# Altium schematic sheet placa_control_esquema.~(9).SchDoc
size A4
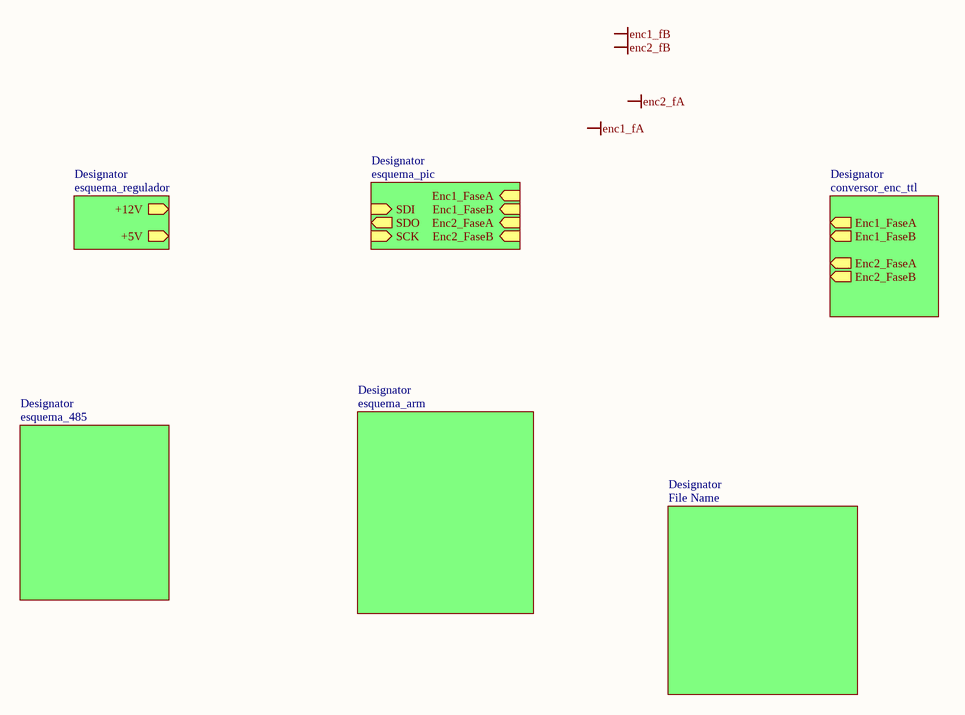
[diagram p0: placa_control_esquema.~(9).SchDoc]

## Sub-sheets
Designator = esquema_regulador: +12V (out), +5V (out)
Designator = esquema_pic: SDI (in), SDO (out), SCK (in), Enc1_FaseA (in), Enc1_FaseB (in), Enc2_FaseA (in), Enc2_FaseB (in)
Designator = esquema_485: no entries
Designator = esquema_arm: no entries
Designator = File Name: no entries
Designator = conversor_enc_ttl: Enc1_FaseA (out), Enc1_FaseB (out), Enc2_FaseA (out), Enc2_FaseB (out)

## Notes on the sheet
- Labels drawn without touching a wire or pin: enc1_fA, enc1_fB, enc2_fA, enc2_fB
